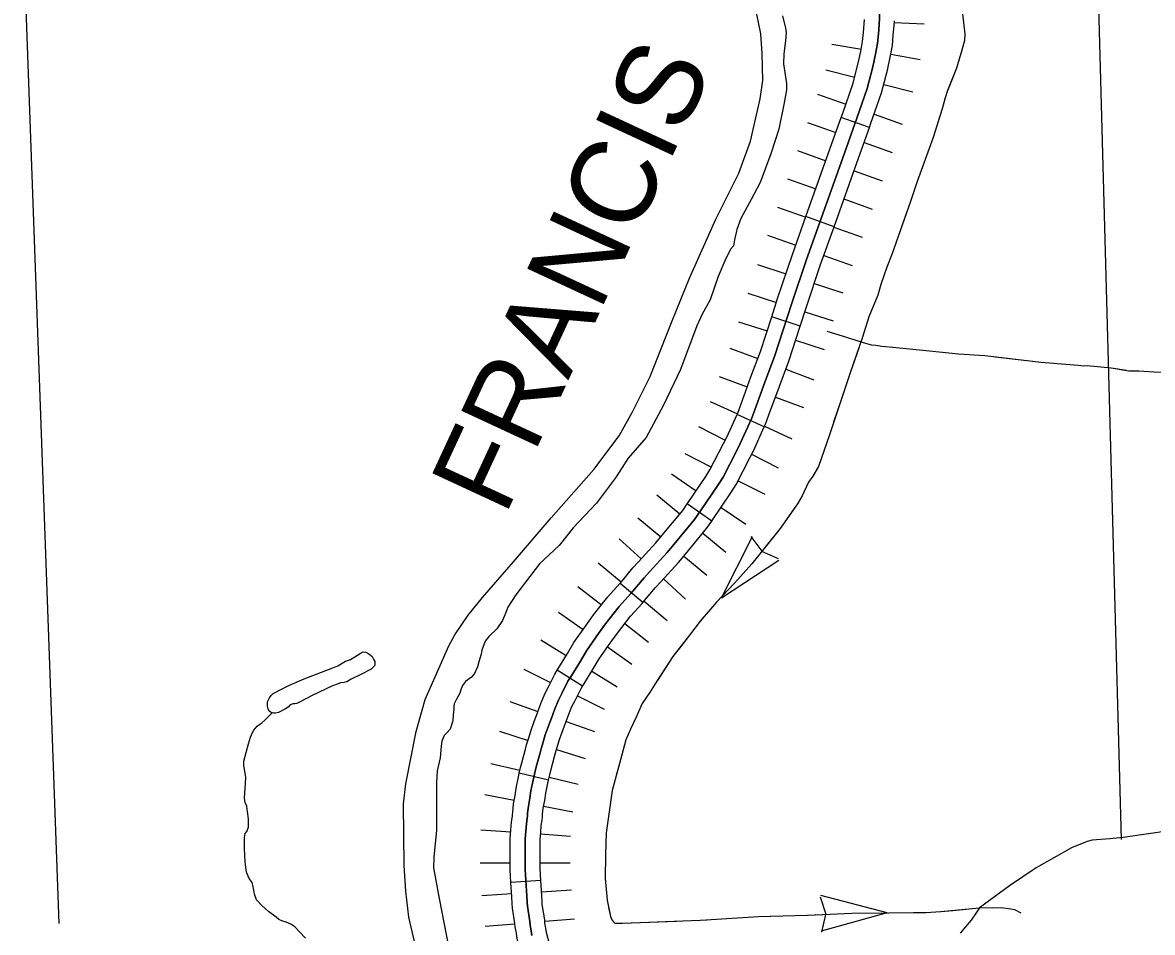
# Model space of a CAD drawing. Extents: x 1720274 to 1751788, y 372074 to 391887.
# Drawn here: x 1732620 to 1733514, y 375288 to 376008 of the extents above; entities that cross this region are included whole.
import ezdxf

# ---------------------------------------------------------------- set-up
doc = ezdxf.new("R2010")
doc.units = 0
for name, color, linetype in [('Level 29', 7, 'Continuous'), ('Level 32', 7, 'Continuous'), ('Level 35', 7, 'Continuous'), ('Level 43', 7, 'Continuous'), ('Level 5', 7, 'Continuous')]:
    doc.layers.add(name, color=color, linetype=linetype)

msp = doc.modelspace()

# ---------------------------------------------------------------- linework, layer by layer
at = {"layer": 'Level 29'}
for p, q in [((1733309.8, 376007.91), (1733333.48, 376006.88)), ((1733260.39, 375990.96), (1733283.74, 375986.91)), ((1733260.39, 375990.96), (1733283.74, 375986.91)), ((1733307.09, 375982.85), (1733330.44, 375978.79)), ((1733307.09, 375982.85), (1733330.44, 375978.79)), ((1733255.58, 375970.62), (1733278.54, 375964.75)), ((1733301.5, 375958.87), (1733324.46, 375952.99)), ((1733249.13, 375951.19), (1733271.47, 375943.27)), ((1733241.21, 375928.83), (1733263.55, 375920.92)), ((1733241.21, 375928.83), (1733263.55, 375920.92)), ((1733293.8, 375935.34), (1733316.14, 375927.42)), ((1733285.89, 375913.01), (1733308.23, 375905.1)), ((1733285.89, 375913.01), (1733308.23, 375905.1)), ((1733233.3, 375906.57), (1733255.63, 375898.61)), ((1733225.35, 375884.25), (1733247.67, 375876.29)), ((1733277.95, 375890.66), (1733300.28, 375882.7)), ((1733270, 375868.33), (1733292.32, 375860.37)), ((1733217.39, 375861.92), (1733239.71, 375853.96)), ((1733217.39, 375861.92), (1733239.71, 375853.96)), ((1733209.43, 375839.6), (1733231.76, 375831.64)), ((1733262.04, 375846.01), (1733284.36, 375838.05)), ((1733262.04, 375846.01), (1733284.36, 375838.05)), ((1733254.08, 375823.68), (1733276.41, 375815.73)), ((1733201.54, 375816.53), (1733224.01, 375809)), ((1733246.48, 375801.47), (1733268.96, 375793.94)), ((1733193.94, 375793.74), (1733216.48, 375786.42)), ((1733193.94, 375793.74), (1733216.48, 375786.42)), ((1733239.02, 375779.09), (1733261.56, 375771.77)), ((1733239.02, 375779.09), (1733261.56, 375771.77)), ((1733186.61, 375771.2), (1733209.15, 375763.88)), ((1733179.54, 375750.25), (1733201.73, 375741.93)), ((1733231.69, 375756.55), (1733254.23, 375749.23)), ((1733223.92, 375733.61), (1733246.12, 375725.29)), ((1733171.19, 375727.82), (1733193.44, 375719.65)), ((1733171.19, 375727.82), (1733193.44, 375719.65)), ((1733164.05, 375708.1), (1733185.6, 375698.25)), ((1733215.68, 375711.47), (1733237.93, 375703.3)), ((1733215.68, 375711.47), (1733237.93, 375703.3)), ((1733154.85, 375688.27), (1733175.87, 375677.32)), ((1733207.15, 375688.4), (1733228.71, 375678.54)), ((1733143.91, 375666.94), (1733165.01, 375656.15)), ((1733143.91, 375666.94), (1733165.01, 375656.15)), ((1733196.88, 375666.36), (1733217.9, 375655.41)), ((1733133.34, 375650.67), (1733152.99, 375637.42)), ((1733186.11, 375645.35), (1733207.21, 375634.56)), ((1733186.11, 375645.35), (1733207.21, 375634.56)), ((1733121.71, 375634.13), (1733139.97, 375619.03)), ((1733106.67, 375615.94), (1733124.89, 375600.79)), ((1733106.67, 375615.94), (1733124.89, 375600.79)), ((1733172.64, 375624.17), (1733192.29, 375610.92)), ((1733091.97, 375599.44), (1733109.5, 375583.48)), ((1733158.24, 375603.93), (1733176.51, 375588.82)), ((1733075.46, 375580.41), (1733093.64, 375565.21)), ((1733143.11, 375585.64), (1733161.34, 375570.49)), ((1733143.11, 375585.64), (1733161.34, 375570.49)), ((1733127.02, 375567.53), (1733144.55, 375551.57)), ((1733059.39, 375561.68), (1733077.99, 375546.99)), ((1733059.39, 375561.68), (1733077.99, 375546.99)), ((1733111.82, 375550.01), (1733130, 375534.8)), ((1733044.05, 375541.18), (1733063.41, 375527.51)), ((1733096.59, 375532.3), (1733115.19, 375517.61)), ((1733096.59, 375532.3), (1733115.19, 375517.61)), ((1733029.99, 375519.4), (1733050.17, 375506.98)), ((1733082.77, 375513.84), (1733102.13, 375500.18)), ((1733016.57, 375496.18), (1733037.77, 375485.59)), ((1733016.57, 375496.18), (1733037.77, 375485.59)), ((1733070.36, 375494.56), (1733090.55, 375482.15)), ((1733058.97, 375475), (1733080.18, 375464.41)), ((1733058.97, 375475), (1733080.18, 375464.41)), ((1733005.4, 375470.48), (1733027.74, 375462.57)), ((1733050.08, 375454.66), (1733072.42, 375446.75)), ((1732997.31, 375446.95), (1733019.9, 375439.8)), ((1733042.5, 375432.65), (1733065.09, 375425.49)), ((1732990.44, 375421.59), (1733013.49, 375416.1)), ((1732990.44, 375421.59), (1733013.49, 375416.1)), ((1733036.55, 375410.6), (1733059.6, 375405.11)), ((1733036.55, 375410.6), (1733059.6, 375405.11)), ((1732985.69, 375397), (1733008.94, 375392.39)), ((1733032.19, 375387.78), (1733055.43, 375383.17)), ((1732982.52, 375369.04), (1733006.17, 375367.38)), ((1733029.81, 375365.72), (1733053.45, 375364.06)), ((1732982.07, 375342.93), (1733005.77, 375342.88)), ((1732982.07, 375342.93), (1733005.77, 375342.88)), ((1733029.47, 375342.84), (1733053.17, 375342.79)), ((1733029.47, 375342.84), (1733053.17, 375342.79)), ((1733030.57, 375319.92), (1733054.22, 375321.37)), ((1732983.26, 375317.02), (1733006.91, 375318.47)), ((1732985.91, 375292.66), (1733009.53, 375294.66)), ((1733033.14, 375296.66), (1733056.76, 375298.66))]:
    msp.add_line(p, q, dxfattribs=at)
for points in [[(1733298.35, 376017.48), (1733297.87, 376006.26), (1733297.26, 375998.94), (1733296.53, 375991.25), (1733295.06, 375982.84), (1733292.87, 375972.95), (1733288.47, 375955.74), (1733280.15, 375932.31), (1733270.3, 375904.49), (1733240.33, 375820.39), (1733228.73, 375785.79), (1733215.07, 375743.74), (1733207.45, 375723.44), (1733199.38, 375701.46), (1733196.87, 375694.4), (1733187.87, 375674.7), (1733185.08, 375669.36), (1733174.22, 375648.13), (1733170.46, 375642.13), (1733156.49, 375621.41), (1733151.75, 375614.68), (1733135.28, 375594.74), (1733129.98, 375588.38), (1733116.15, 375573.19), (1733111.83, 375568.49), (1733101.34, 375555.95), (1733092.06, 375545.68), (1733081.2, 375531.93), (1733075.72, 375524.4), (1733066.11, 375510.79), (1733061.29, 375502.43), (1733053.63, 375489.98), (1733051.49, 375486.54), (1733046.62, 375476.78), (1733043.88, 375471.72), (1733041.09, 375464.79), (1733038.49, 375457.45), (1733035.8, 375450.44), (1733033.53, 375444.26), (1733031.67, 375437.71), (1733030.19, 375433.02), (1733029.44, 375429.95), (1733026.43, 375418.98), (1733025.5, 375415.36), (1733023.83, 375408.35), (1733022.15, 375399.94), (1733021.37, 375394.13), (1733020.11, 375387.81), (1733019.56, 375382.1), (1733019.51, 375380.19), (1733019.23, 375378.29), (1733018.58, 375373.73), (1733018.07, 375367.74), (1733017.65, 375361.79), (1733017.61, 375337.68), (1733018.91, 375316.49)], [(1733018.91, 375316.49), (1733019.14, 375311.43), (1733019.42, 375308.55), (1733021.27, 375296.38), (1733021.51, 375293.63), (1733022.29, 375289.13), (1733022.94, 375285.22)]]:
    msp.add_lwpolyline(points, dxfattribs=at)
at = {"layer": 'Level 32'}
for p, q in [((1733290.14, 375925.01), (1733267.8, 375932.92)), ((1733262.17, 375846.39), (1733239.85, 375854.35)), ((1733235.33, 375767.76), (1733212.79, 375775.09)), ((1733206.93, 375687.9), (1733185.38, 375697.76)), ((1733165.29, 375613.33), (1733145.9, 375626.96)), ((1733110.87, 375548.86), (1733092.69, 375564.07)), ((1733063.09, 375482.76), (1733042.96, 375495.26)), ((1733035.98, 375408.23), (1733012.93, 375413.72)), ((1733030.02, 375328.84), (1733006.36, 375327.39))]:
    msp.add_line(p, q, dxfattribs=at)
for points in [[(1733018.91, 375316.49), (1733017.61, 375337.68), (1733017.65, 375361.79), (1733018.07, 375367.74), (1733018.58, 375373.73), (1733019.23, 375378.29), (1733019.51, 375380.19), (1733019.56, 375382.1), (1733020.11, 375387.81), (1733021.37, 375394.13), (1733022.15, 375399.94), (1733023.83, 375408.35), (1733025.5, 375415.36), (1733026.43, 375418.98), (1733029.44, 375429.95), (1733030.19, 375433.02), (1733031.67, 375437.71), (1733033.53, 375444.26), (1733035.8, 375450.44), (1733038.49, 375457.45), (1733041.09, 375464.79), (1733043.88, 375471.72), (1733046.62, 375476.78), (1733051.49, 375486.54), (1733053.63, 375489.98), (1733061.29, 375502.43), (1733066.11, 375510.79), (1733075.72, 375524.4), (1733081.2, 375531.93), (1733092.06, 375545.68), (1733101.34, 375555.95), (1733111.83, 375568.49), (1733116.15, 375573.19), (1733129.98, 375588.38), (1733135.28, 375594.74), (1733151.75, 375614.68), (1733156.49, 375621.41), (1733170.46, 375642.13), (1733174.22, 375648.13), (1733185.08, 375669.36), (1733187.87, 375674.7), (1733196.87, 375694.4), (1733199.38, 375701.46), (1733207.45, 375723.44), (1733215.07, 375743.74), (1733228.73, 375785.79), (1733240.33, 375820.39), (1733270.3, 375904.49), (1733280.15, 375932.31), (1733288.47, 375955.74), (1733292.87, 375972.95), (1733295.06, 375982.84), (1733296.53, 375991.25), (1733297.26, 375998.94), (1733297.87, 376006.26), (1733298.35, 376017.48)], [(1733267.8, 375932.92), (1733268.98, 375936.26), (1733277.12, 375959.2), (1733281.34, 375975.71), (1733283.44, 375985.13), (1733284.77, 375992.83), (1733285.45, 375999.99), (1733286.04, 376007), (1733286.18, 376010.29)], [(1733290.14, 375925.01), (1733291.32, 375928.35), (1733299.81, 375952.28), (1733304.4, 375970.2), (1733306.69, 375980.54), (1733308.28, 375989.67), (1733309.06, 375997.88), (1733309.7, 376005.51), (1733309.86, 376009.26)], [(1733239.85, 375854.35), (1733259.14, 375908.46), (1733267.8, 375932.92)], [(1733262.17, 375846.39), (1733281.47, 375900.53), (1733290.14, 375925.01)], [(1733212.79, 375775.09), (1733217.48, 375789.5), (1733229.13, 375824.27), (1733239.85, 375854.35)], [(1733235.33, 375767.76), (1733239.98, 375782.08), (1733251.53, 375816.52), (1733262.17, 375846.39)], [(1733185.38, 375697.76), (1733185.88, 375698.86), (1733188.23, 375705.49), (1733196.35, 375727.56), (1733203.88, 375747.66), (1733212.79, 375775.09)], [(1733206.93, 375687.9), (1733207.87, 375689.95), (1733210.52, 375697.44), (1733218.56, 375719.32), (1733226.26, 375739.83), (1733235.33, 375767.76)], [(1733145.9, 375626.96), (1733146.73, 375628.13), (1733160.53, 375648.6), (1733163.91, 375653.99), (1733174.55, 375674.8), (1733177.22, 375679.91), (1733185.38, 375697.76)], [(1733165.29, 375613.33), (1733166.25, 375614.69), (1733180.39, 375635.67), (1733184.53, 375642.27), (1733195.61, 375663.92), (1733198.52, 375669.5), (1733206.93, 375687.9)], [(1733092.69, 375564.07), (1733102.92, 375576.31), (1733107.41, 375581.19), (1733121.04, 375596.16), (1733126.15, 375602.31), (1733142.33, 375621.87), (1733145.9, 375626.96)], [(1733110.87, 375548.86), (1733120.74, 375560.68), (1733124.89, 375565.19), (1733138.93, 375580.6), (1733144.4, 375587.18), (1733161.18, 375607.48), (1733165.29, 375613.33)], [(1733042.96, 375495.26), (1733043.55, 375496.21), (1733051.11, 375508.5), (1733056.12, 375517.18), (1733066.09, 375531.31), (1733071.75, 375539.09), (1733083.01, 375553.34), (1733092.4, 375563.73), (1733092.69, 375564.07)], [(1733063.09, 375482.76), (1733063.71, 375483.75), (1733071.47, 375496.36), (1733076.11, 375504.4), (1733085.35, 375517.5), (1733090.64, 375524.77), (1733101.11, 375538.03), (1733110.29, 375548.17), (1733110.87, 375548.86)], [(1733012.93, 375413.73), (1733013.99, 375418.2), (1733014.97, 375422.03), (1733017.97, 375432.92), (1733018.76, 375436.2), (1733020.32, 375441.11), (1733022.25, 375447.93), (1733024.71, 375454.61), (1733027.38, 375461.56), (1733030.01, 375468.99), (1733033.14, 375476.76), (1733036.1, 375482.25), (1733041.14, 375492.32), (1733042.96, 375495.26)], [(1733035.98, 375408.23), (1733037, 375412.52), (1733037.88, 375415.94), (1733040.92, 375426.98), (1733041.61, 375429.83), (1733043.02, 375434.3), (1733044.8, 375440.59), (1733046.89, 375446.27), (1733049.61, 375453.35), (1733052.18, 375460.6), (1733054.62, 375466.67), (1733057.13, 375471.31), (1733061.85, 375480.75), (1733063.09, 375482.76)], [(1733006.36, 375327.39), (1733005.76, 375337.33), (1733005.8, 375362.22), (1733006.26, 375368.66), (1733006.8, 375375.07), (1733007.5, 375379.98), (1733007.68, 375381.2), (1733007.72, 375382.82), (1733008.38, 375389.54), (1733009.67, 375396.08), (1733010.46, 375401.89), (1733012.25, 375410.87), (1733012.93, 375413.72)], [(1733030.02, 375328.84), (1733029.46, 375338.03), (1733029.5, 375361.36), (1733029.88, 375366.82), (1733030.36, 375372.39), (1733030.96, 375376.59), (1733031.34, 375379.19), (1733031.39, 375381.37), (1733031.85, 375386.08), (1733033.06, 375392.18), (1733033.85, 375397.98), (1733035.41, 375405.82), (1733035.98, 375408.23)], [(1733020.37, 375243.17), (1733019.95, 375244.89), (1733018.05, 375251.45), (1733013.75, 375273.53), (1733011.34, 375282.75), (1733010.61, 375287.13), (1733009.74, 375292.11), (1733009.5, 375294.98), (1733007.65, 375307.08), (1733007.31, 375310.59), (1733007.07, 375315.86), (1733006.36, 375327.39)], [(1733043.37, 375248.9), (1733042.84, 375251.04), (1733041.11, 375257.02), (1733036.87, 375278.8), (1733034.54, 375287.7), (1733033.98, 375291.12), (1733033.27, 375295.16), (1733033.05, 375297.77), (1733031.18, 375310.01), (1733030.96, 375312.27), (1733030.74, 375317.13), (1733030.02, 375328.84)], [(1733022.94, 375285.22), (1733022.29, 375289.13), (1733021.51, 375293.63), (1733021.27, 375296.38), (1733019.42, 375308.55), (1733019.14, 375311.43), (1733018.91, 375316.49)]]:
    msp.add_lwpolyline(points, dxfattribs=at)
at = {"layer": 'Level 35'}
for points in [[(1732931.79, 375272.73), (1732925.46, 375299.91), (1732923.19, 375320.53), (1732921.84, 375340.69), (1732921.16, 375389.62), (1732923.19, 375405.48), (1732931.34, 375446.71), (1732938.36, 375472.08), (1732957.14, 375514.67), (1732961.9, 375523.28), (1732972.53, 375538.91), (1732983.85, 375552.95), (1733008.29, 375581.04), (1733038.17, 375615.93), (1733071.89, 375654.21), (1733092.03, 375680.72), (1733102.67, 375699.75), (1733116.47, 375727.84), (1733133.9, 375771.79), (1733147.7, 375805.54), (1733168.53, 375852.43), (1733186.63, 375888.68), (1733195.91, 375914.05), (1733203.61, 375947.58), (1733205.64, 375962.08), (1733205.19, 375983.37), (1733204.06, 375999), (1733200.21, 376018.26)], [(1733221.2, 376013.33), (1733223.81, 376003.39), (1733224.16, 376000.07), (1733223.81, 375993.61), (1733222.42, 375983.14), (1733222.24, 375975.29), (1733224.51, 375959.58), (1733224.51, 375954.7), (1733222.42, 375943), (1733218.41, 375923.46), (1733212.13, 375904.09), (1733203.59, 375881.4), (1733196.61, 375867.96), (1733188.42, 375852.78), (1733185.28, 375844.23), (1733183.19, 375836.02), (1733182.49, 375831.14), (1733180.4, 375828.87), (1733176.39, 375821.19), (1733170.28, 375807.05), (1733164.18, 375788.55), (1733157.73, 375777.04), (1733153.37, 375767.96), (1733140.47, 375733.23), (1733127.05, 375705.13), (1733113.45, 375679.65), (1733099.15, 375663.25), (1733089.21, 375647.54), (1733074.04, 375627.65), (1733055.56, 375608.1), (1733044.58, 375593.96), (1733029.06, 375579.48), (1733010.23, 375555.05), (1733003.95, 375545.1), (1733002.21, 375541.08), (1732999.59, 375534.63), (1732995.06, 375528), (1732988.96, 375521.89), (1732985.82, 375518.22)], [(1732985.82, 375518.22), (1732983.38, 375511.24), (1732982.85, 375508.1), (1732980.94, 375501.99), (1732979.89, 375497.98), (1732977.45, 375492.74), (1732975.01, 375489.95), (1732970.48, 375486.46), (1732968.03, 375483.32), (1732966.99, 375480.7), (1732965.94, 375477.21), (1732963.15, 375472.32), (1732961.41, 375468.83), (1732961.06, 375466.91), (1732961.23, 375464.12), (1732960.71, 375460.28), (1732960.36, 375455.22), (1732958.1, 375448.76), (1732955.83, 375446.15), (1732953.39, 375443.7), (1732951.65, 375439.16), (1732951.12, 375435.33), (1732950.25, 375426.08), (1732947.81, 375415.6), (1732947.29, 375406.36), (1732947.46, 375390.65), (1732947.46, 375368.83), (1732945.37, 375347.37), (1732945.02, 375338.99), (1732949.38, 375314.56), (1732957.05, 375275.29)], [(1732842.57, 375488.62), (1732856.35, 375493.77), (1732865.35, 375497.08), (1732869.21, 375498.92), (1732875.46, 375502.6), (1732879.32, 375503.7), (1732882.62, 375505.91), (1732886.98, 375508.55), (1732888.65, 375509.7), (1732889.49, 375509.91), (1732891.47, 375509.7), (1732893.87, 375508.24), (1732896.38, 375506.15), (1732897.84, 375503.64), (1732898.67, 375502.18), (1732898.67, 375500.61), (1732898.67, 375499.67), (1732898.36, 375498.83), (1732897.11, 375497.47), (1732895.65, 375496.11), (1732887.61, 375491.83), (1732879.78, 375488.17), (1732876.33, 375486.19), (1732874.35, 375485.67), (1732871.43, 375485.46), (1732869.55, 375484.52), (1732864.96, 375482.84), (1732849.09, 375475.32), (1732839.38, 375470.2), (1732836.77, 375468.95), (1732835.2, 375468.84), (1732833.74, 375468.74), (1732832.28, 375468.32), (1732831.55, 375468.01), (1732829.88, 375466.12), (1732827.89, 375464.87), (1732822.26, 375461.84), (1732820.07, 375461.42), (1732818.5, 375461.42), (1732817.56, 375461.63), (1732816.1, 375462.05), (1732815.05, 375462.89), (1732814.11, 375464.87), (1732813.49, 375466.86), (1732813.7, 375470.2), (1732815.26, 375473.44), (1732816.52, 375475.32), (1732818.19, 375476.89), (1732824.24, 375480.02), (1732831.13, 375483.37), (1732842.57, 375488.62)], [(1732843.7, 375283.3), (1732838.77, 375288.49), (1732835.14, 375292.13), (1732832.02, 375294.21), (1732828.39, 375296.03), (1732825.01, 375297.07), (1732822.68, 375298.11), (1732820.34, 375299.92), (1732814.44, 375304.4), (1732809.02, 375309.18), (1732805.02, 375313.7), (1732803.34, 375317.97), (1732802.83, 375321.33), (1732801.92, 375325.2), (1732801.41, 375327.4), (1732799.21, 375330.5), (1732796.89, 375335.41), (1732796.63, 375337.34), (1732795.99, 375343.55), (1732795.47, 375354.14), (1732795.34, 375362.92), (1732795.86, 375366.15), (1732797.15, 375367.7), (1732798.57, 375371.08), (1732798.57, 375373.56), (1732798.57, 375377.39), (1732797.95, 375381.52), (1732797.85, 375383.59), (1732797.12, 375387.83), (1732795.99, 375390.62), (1732795.68, 375392.27), (1732795.37, 375394.34), (1732796.09, 375405.61), (1732796.5, 375410.78), (1732795.99, 375413.77), (1732795.16, 375418.32), (1732794.95, 375420.18), (1732794.95, 375423.28), (1732796.82, 375430.14), (1732798.66, 375436.95), (1732800.13, 375442.28), (1732801.6, 375445.96), (1732802.89, 375447.8), (1732805.46, 375451.11), (1732809.13, 375453.68), (1732811.52, 375455.89), (1732813.91, 375458.28), (1732817.33, 375461.7)], [(1733527.34, 375368.24), (1733490.93, 375363.03), (1733480.52, 375361.9), (1733466.5, 375360.77), (1733462.43, 375359.64), (1733450.22, 375354.65), (1733422.17, 375339.03), (1733401.14, 375324.77), (1733377.16, 375307.34), (1733374.67, 375303.26), (1733370.6, 375297.38), (1733366.31, 375292.17), (1733362.01, 375287.19)]]:
    msp.add_lwpolyline(points, dxfattribs=at)
at = {"layer": 'Level 43'}
for p, q in [((1733173.08, 375552.66), (1733197.44, 375601.11)), ((1733196.34, 375601.1), (1733204.87, 375589.46)), ((1733218.22, 375583.52), (1733205.02, 375589.34)), ((1733173.08, 375552.66), (1733218.4, 375582.44)), ((1733251.09, 375315.94), (1733255.52, 375302.21)), ((1733304.14, 375303.39), (1733251.63, 375316.94)), ((1733304.14, 375303.39), (1733251.89, 375288.88)), ((1733252.49, 375287.91), (1733255.53, 375302.02))]:
    msp.add_line(p, q, dxfattribs=at)
for points in [[(1733363.81, 376014.92), (1733365.68, 375998.63), (1733365.39, 375993.73), (1733363.23, 375986.09), (1733359.05, 375971.95), (1733352, 375954.08), (1733350.12, 375948.45), (1733347.72, 375939.57), (1733340.57, 375917.08), (1733328.05, 375882.19), (1733322.56, 375866.34), (1733307.88, 375824.42), (1733304.05, 375814.45), (1733299.2, 375800.52), (1733296.9, 375792.09), (1733289.75, 375774.96), (1733284.77, 375758.86), (1733274.56, 375729.98), (1733267.15, 375707.87), (1733258.47, 375681.54), (1733254.13, 375668.64), (1733249.92, 375656.62), (1733245.32, 375648.83), (1733242, 375644.23), (1733236.89, 375633.24), (1733233.32, 375627.1), (1733219.53, 375607.55), (1733196.93, 375579.43), (1733183.27, 375564.1), (1733168.97, 375549.27), (1733156.2, 375534.19), (1733147.65, 375522.95), (1733134.63, 375506.2), (1733121.86, 375486.65), (1733116.62, 375478.22), (1733110.11, 375468.89), (1733105.52, 375458.15), (1733100.91, 375448.78), (1733097.17, 375440.21), (1733093.15, 375424.42), (1733086.47, 375400.05), (1733082.99, 375375.96), (1733081.65, 375366.59), (1733081.12, 375349.18), (1733080.85, 375330.57), (1733082.46, 375313.31), (1733085.13, 375300.32), (1733086.2, 375297.78), (1733087.4, 375296.04), (1733088.61, 375295.23), (1733089.95, 375295.23), (1733094.76, 375295.23), (1733156.15, 375297.51), (1733164.97, 375297.91), (1733202.29, 375300.32), (1733241.07, 375301.39), (1733276.11, 375303.13), (1733334.69, 375303.67), (1733346.72, 375304.34), (1733377.08, 375307.15), (1733394.47, 375307.55), (1733402.22, 375306.48), (1733405.07, 375305.83), (1733410.04, 375303.36)], [(1733363.6, 375987.38), (1733363.23, 375986.09), (1733359.05, 375971.95), (1733353.47, 375957.82)], [(1733353.47, 375957.82), (1733352, 375954.08), (1733350.12, 375948.45), (1733347.72, 375939.57), (1733344.04, 375928.01)], [(1733337.4, 375908.24), (1733328.05, 375882.19), (1733322.56, 375866.34), (1733316.57, 375849.24)], [(1733309.68, 375829.56), (1733307.88, 375824.42), (1733304.05, 375814.45), (1733299.2, 375800.52), (1733296.9, 375792.09), (1733289.75, 375774.96), (1733288.45, 375770.76)], [(1733256.31, 375763.67), (1733268.61, 375759.88), (1733284.32, 375754.96), (1733291.51, 375752.87), (1733295.11, 375752.68), (1733299.84, 375751.93), (1733311.19, 375750.79), (1733332.39, 375748.71), (1733347.9, 375747.19), (1733360.58, 375745.87), (1733381.59, 375744.35), (1733426.06, 375739.05), (1733455.39, 375736.77), (1733459.56, 375736.2), (1733462.59, 375736.39)], [(1733256.31, 375763.67), (1733268.61, 375759.88), (1733284.32, 375754.96), (1733286.19, 375754.41)], [(1733281.97, 375750.94), (1733274.56, 375729.98), (1733267.15, 375707.87), (1733261.82, 375691.71)], [(1733306.73, 375751.24), (1733311.19, 375750.79), (1733332.39, 375748.71), (1733347.9, 375747.19), (1733360.58, 375745.87), (1733369.01, 375745.26)], [(1733389.77, 375743.37), (1733426.06, 375739.05), (1733452.01, 375737.04)], [(1733462.59, 375736.39), (1733481.52, 375734.77), (1733495.61, 375732.34), (1733503.54, 375732.34), (1733515.21, 375731.46), (1733532.83, 375730.8), (1733540.09, 375729.04), (1733558.59, 375726.61), (1733576.2, 375724.63), (1733592.5, 375723.75), (1733609.45, 375721.32), (1733642.04, 375718.24), (1733668.46, 375715.81), (1733704.13, 375711.63), (1733714.7, 375710.53), (1733738.7, 375706.34), (1733756.54, 375704.13)], [(1733462.59, 375736.39), (1733481.52, 375734.77), (1733493.62, 375732.69)], [(1733255.23, 375671.92), (1733254.13, 375668.64), (1733249.92, 375656.62), (1733245.32, 375648.83), (1733242, 375644.23), (1733236.89, 375633.24), (1733233.32, 375627.1), (1733226.16, 375616.95)], [(1733213.67, 375600.25), (1733196.93, 375579.43), (1733183.27, 375564.1), (1733172.64, 375553.07)], [(1733158.91, 375537.39), (1733156.2, 375534.19), (1733147.65, 375522.95), (1733139.69, 375512.71)], [(1733139.69, 375512.71), (1733134.63, 375506.2), (1733122.03, 375486.91)], [(1733110.55, 375469.51), (1733110.11, 375468.89), (1733105.52, 375458.15), (1733100.91, 375448.78), (1733097.17, 375440.21), (1733093.15, 375424.42), (1733089.44, 375410.87)], [(1733085.09, 375390.52), (1733082.99, 375375.96), (1733081.65, 375366.59), (1733081.12, 375349.18), (1733080.85, 375330.57), (1733081.07, 375328.22)], [(1733083.64, 375307.54), (1733085.13, 375300.32), (1733086.2, 375297.78), (1733087.4, 375296.04), (1733088.61, 375295.23), (1733089.95, 375295.23), (1733094.76, 375295.23), (1733137.45, 375296.82)], [(1733241.61, 375301.42), (1733276.11, 375303.13), (1733304.14, 375303.39)], [(1733324.99, 375303.58), (1733334.69, 375303.67), (1733346.72, 375304.34), (1733356.22, 375305.22)], [(1733356.22, 375305.22), (1733377.08, 375307.15), (1733387.41, 375307.39)], [(1733158.29, 375297.61), (1733164.97, 375297.91), (1733202.29, 375300.32), (1733220.77, 375300.83)]]:
    msp.add_lwpolyline(points, dxfattribs=at)
at = {"layer": 'Level 5'}
for points in [[(1733468.17, 376146.69), (1733489.48, 375361.29)], [(1732619.72, 376092.07), (1732648.33, 375294.93)]]:
    msp.add_lwpolyline(points, dxfattribs=at)

# ---------------------------------------------------------------- texts
at = {"layer": 'Level 35'}
msp.add_text('FRANCIS', height=66.739, rotation=65.10573, dxfattribs=at).set_placement((1733001.59, 375616.5))

doc.saveas('drawing.dxf')
